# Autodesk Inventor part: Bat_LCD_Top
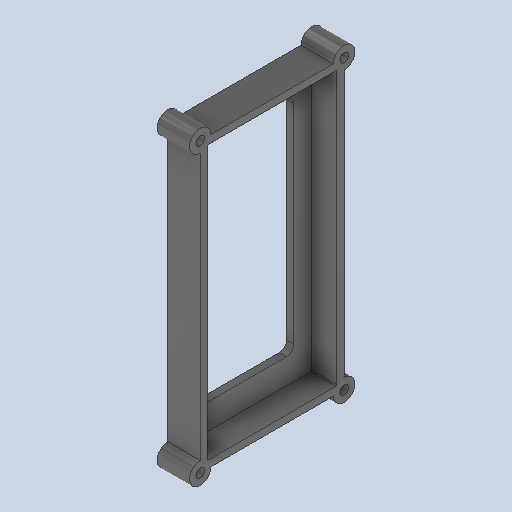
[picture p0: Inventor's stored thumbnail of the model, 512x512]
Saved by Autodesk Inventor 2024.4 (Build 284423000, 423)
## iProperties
Created: 2025-05
Part Number: Bat_LCD_Top
Material: Generic
Document SubType Name: Modeling
Designer: AdminForWorker
Density: 1 g/cm^3
Appearance: Default
Title: Bat_LCD_Top
Author: AdminForWorker
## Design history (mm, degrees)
feature "Body2"
body "Solid1"
